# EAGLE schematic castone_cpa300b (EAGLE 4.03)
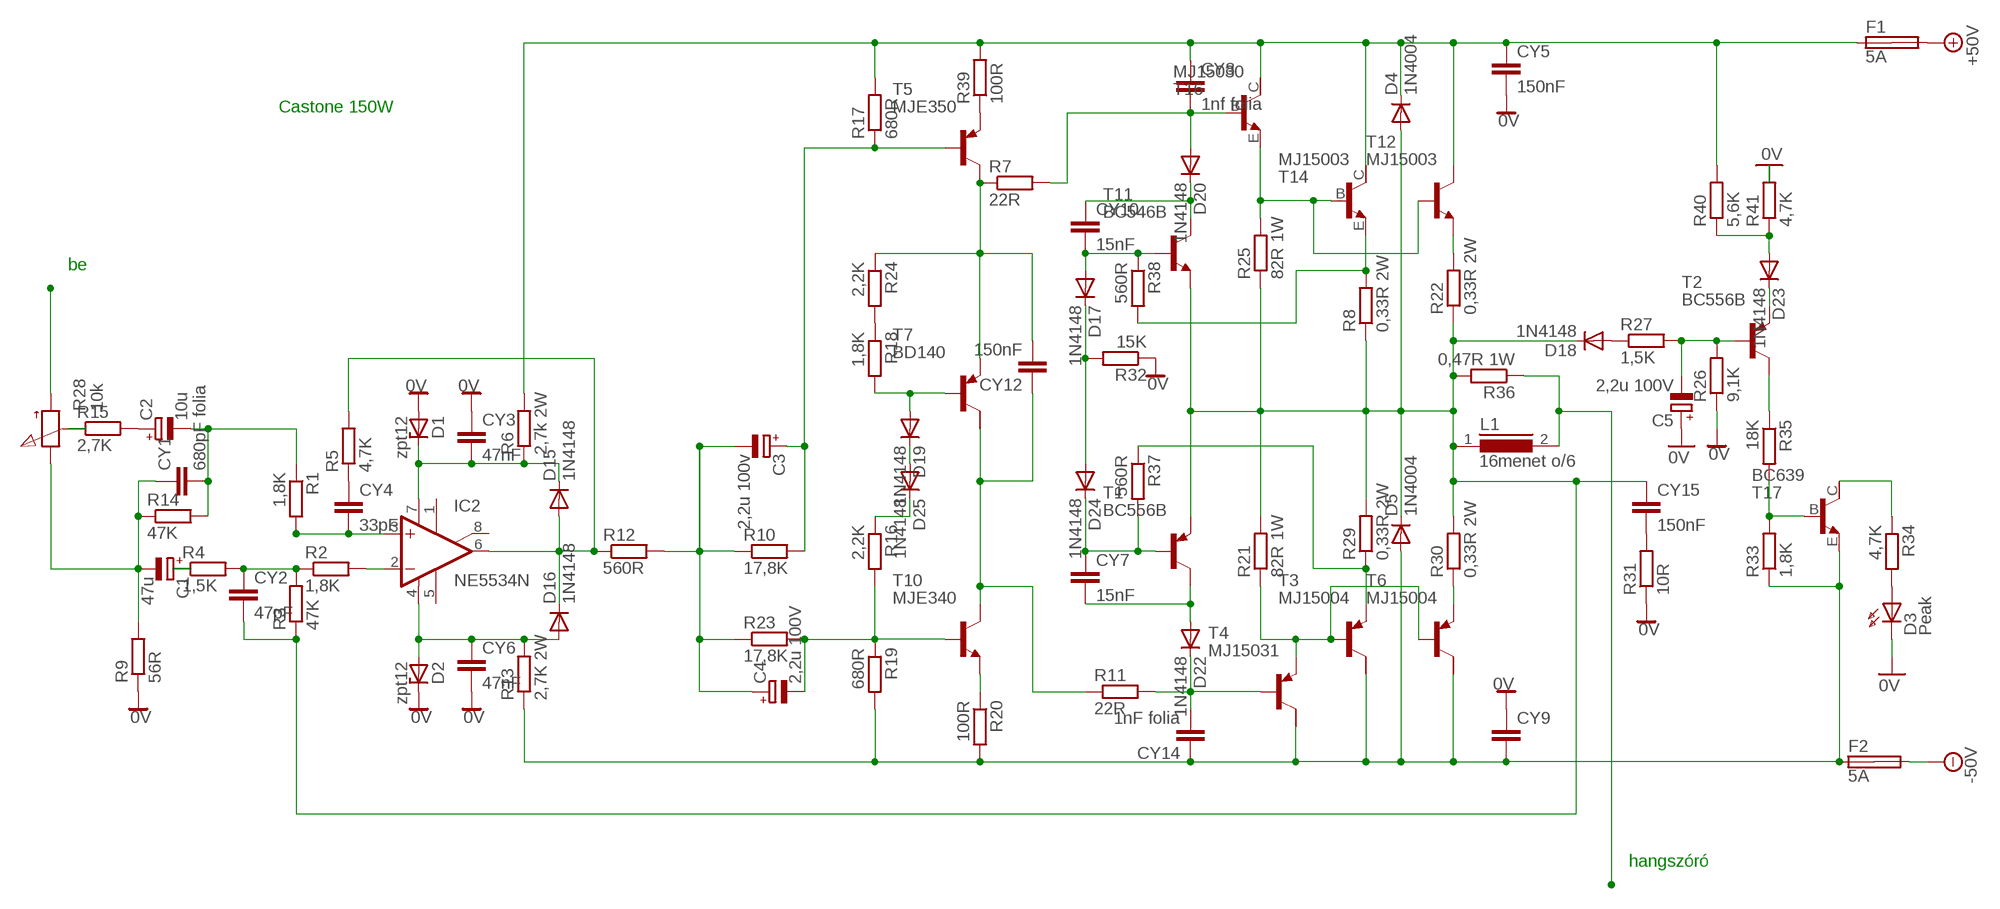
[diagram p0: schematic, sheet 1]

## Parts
C1  47u  CPOL-EUTT6D6  [TT5D6]
C2  10u  CPOL-EUTT6D6  [TT5D6]
C3  2,2u 100v  CPOL-EUTT6D6  [TT5D6]
C4  2,2u 100V  CPOL-EUTT6D6  [TT5D6]
C5  2,2u 100V  CPOL-EUTT6D6  [TT5D6]
CY1  680pF folia  CYYC15B6  [YC15B6]
CY2  47pF  CYYC10B5  [YC10B5]
CY3  47nF  CYYC10B5  [YC10B5]
CY4  33pF  CYYC10B5  [YC10B5]
CY5  150nF  CYYC10B5  [YC10B5]
CY6  47nF  CYYC10B5  [YC10B5]
CY7  15nF  CYYC10B5  [YC10B5]
CY8  1nf folia  CYYC10B5  [YC10B5]
CY9  CYYC10B5  [YC10B5]
CY10  15nF  CYYC10B5  [YC10B5]
CY12  150nF  CYYC10B5  [YC10B5]
CY14  1nF folia  CYYC10B5  [YC10B5]
CY15  150nF  CYYC10B5  [YC10B5]
D1  zpt12  ZTK  [DO35Z10]
D2  zpt12  ZTK  [DO35Z10]
D3  Peak  IRL80A  [IRL80A]
D4  1N4004  [DO41-10]
D5  1N4004  [DO41-10]
D15  1N4148  [DO35-10]
D16  1N4148  [DO35-10]
D17  1N4148  [DO35-10]
D18  1N4148  [DO35-10]
D19  1N4148  [DO35-10]
D20  1N4148  [DO35-10]
D22  1N4148  [DO35-10]
D23  1N4148  [DO35-10]
D24  1N4148  [DO35-10]
D25  1N4148  [DO35-10]
F1  5A  SHK20Q  [SHK20Q]
F2  5A  SHK20Q  [SHK20Q]
IC2  NE5534N  [DIL08]
L1  16menet o/6  SMSC20  [SMSC20]
R1  1,8K  R-EU_V526-0  [V526-0]
R2  1,8K  R-EU_V526-0  [V526-0]
R3  47K  R-EU_V526-0  [V526-0]
R4  1,5K  R-EU_V526-0  [V526-0]
R5  4,7K  R-EU_V526-0  [V526-0]
R6  2,7k 2W  R-EU_V526-0  [V526-0]
R7  22R  R-EU_V526-0  [V526-0]
R8  0,33R 2W  R-EU_0204/5  [0204/5]
R9  56R  R-EU_V526-0  [V526-0]
R10  17,8K  R-EU_V526-0  [V526-0]
R11  22R  R-EU_V526-0  [V526-0]
R12  560R  R-EU_V526-0  [V526-0]
R13  2,7K 2W  R-EU_V526-0  [V526-0]
R14  47K  R-EU_V526-0  [V526-0]
R15  2,7K  R-EU_V526-0  [V526-0]
R16  2,2K  R-EU_V526-0  [V526-0]
R17  680R  R-EU_V526-0  [V526-0]
R18  1,8K  R-EU_V526-0  [V526-0]
R19  680R  R-EU_V526-0  [V526-0]
R20  100R  R-EU_V526-0  [V526-0]
R21  82R 1W  R-EU_V526-0  [V526-0]
R22  0,33R 2W  R-EU_0204/5  [0204/5]
R23  17,8K  R-EU_V526-0  [V526-0]
R24  2,2K  R-EU_V526-0  [V526-0]
R25  82R 1W  R-EU_V526-0  [V526-0]
R26  9,1K  R-EU_V526-0  [V526-0]
R27  1,5K  R-EU_V526-0  [V526-0]
R28  10k  PC25  [PC25]
R29  0,33R 2W  R-EU_0204/5  [0204/5]
R30  0,33R 2W  R-EU_0204/5  [0204/5]
R31  10R  R-EU_0204/5  [0204/5]
R32  15K  R-EU_0204/5  [0204/5]
R33  1,8K  R-EU_0204/5  [0204/5]
R34  4,7K  R-EU_0204/5  [0204/5]
R35  18K  R-EU_0204/5  [0204/5]
R36  0,47R 1W  R-EU_0204/5  [0204/5]
R37  560R  R-EU_0204/5  [0204/5]
R38  560R  R-EU_0204/5  [0204/5]
R39  100R  R-EU_0204/7  [0204/7]
R40  5,6K  R-EU_0204/5  [0204/5]
R41  4,7K  R-EU_0204/5  [0204/5]
T1  BC556B  MJE350  [TO126]
T2  BC556B  MJE350  [TO126]
T3  MJ15004  MJ2955  [TO3]
T4  MJ15031  MJ2955  [TO3]
T5  MJE350  [TO126]
T6  MJ15004  MJ2955  [TO3]
T7  BD140  MJ2955  [TO3]
T10  MJE340  [TO126]
T11  BC546B  MJE340  [TO126]
T12  MJ15003  MJE340  [TO126]
T14  MJ15003  MJ413  [TO3]
T16  MJ15030  MJ413  [TO3]
T17  BC639  MJ413  [TO3]

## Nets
0V: C5.+ CY3.2 CY5.1 CY6.1 CY9.2 D1.A D2.C D3.K(C) R9.1 R26.1 R31.1 R32.1 R41.2
+24V: F1.2A ; supply symbol labelled +50V
-24V: F2.2A ; supply symbol labelled -50V
N$1: IC2.2(-IN) R2.2
N$2: CY4.2 R5.1
N$3: C1.+ R4.1
N$5: CY15.1 R31.2
N$6: CY10.2 D20.C T11.2(C)
N$7: CY3.1 D1.C D15.C IC2.7(V+) R6.1
N$8: CY6.2 D2.A D16.A IC2.4(V-) R13.2
N$9: R15.1 R28.S
N$10: CY4.1 IC2.3(+IN) R1.2
N$11: CY2.2 R2.1 R3.2 R4.2
N$12: D15.A D16.C IC2.6(OUT) R5.2 R12.1
N$13: C2.- CY1.1 R1.1 R14.2
N$14: C1.- CY1.2 R9.2 R14.1 R28.A
N$15: CY2.1 CY15.2 D4.A D5.C D18.C L1.1 R3.1 R8.1 R21.2 R22.1 R25.1 R29.2 R30.2 R36.2 T1.1(E) T11.1(E)
N$16: C2.+ R15.2
N$17: CY12.1 R7.1 R24.1 T5.2(C) T7.E
N$18: C3.- C4.+ R10.1 R12.2 R23.1
N$19: C3.+ R10.2 R17.1 T5.3(B)
N$20: CY14.1 D22.C R11.2 T4.B
N$21: CY5.2 CY8.2 D4.C F1.1A R6.2 R17.2 R39.2 R40.2 T12.2(C) T14.C T16.C
N$22: CY7.1 D22.A T1.2(C)
N$23: C4.- R16.2 R19.1 R23.2 T10.3(B)
N$24: R21.1 T3.B T4.E T6.B
N$25: R20.1 T10.1(E)
N$26: CY9.1 CY14.2 D5.A F2.1A R13.1 R19.2 R20.2 R33.1 T3.C T4.C T6.C T17.E
N$27: D19.C D25.A
N$28: D25.C R16.1
N$29: C5.- R26.2 R27.2 T2.3(B)
N$30: R18.2 T7.B
N$31: R18.1 R24.2
N$32: L1.2 R36.1
N$33: R35.1 T2.2(C)
N$34: R29.1 R37.1 T3.E
N$35: R30.1 T6.E
N$36: R8.2 R38.2 T14.E
N$37: R22.2 T12.1(E)
N$38: CY7.2 D24.C R37.2 T1.3(B)
N$39: R33.2 R35.2 T17.B
N$40: CY8.1 D20.A R7.2 T16.B
N$41: CY10.1 D17.A R38.1 T11.3(B)
N$42: R34.1 T17.C
N$43: D17.C D24.A R32.2
N$44: R25.2 T12.3(B) T14.B T16.E
N$45: D3.A R34.2
N$46: D23.C T2.1(E)
N$47: D23.A R40.1 R41.1
N$48: D18.A R27.1
N$49: R28.E
N$50: R39.1 T5.1(E)
N$51: CY12.2 R11.1 T7.C T10.2(C)
N$52: D19.A
Unconnected: F1.1B F1.2B F2.1B F2.2B IC2.1(ON) IC2.5(CMP) IC2.8(ON/CMP) T3.C/ T4.C/ T6.C/ T7.C/ T14.C/(C) T16.C/(C) T17.C/(C)

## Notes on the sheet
- Castone 150W
- be
- hangszóró

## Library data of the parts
C1-C5 = rcl:CPOL-EU: POLARIZED CAPACITOR, European symbol
CY1-CY10 CY12 CY14 CY15 = rcl:CY: Y CAPACITOR
D1 D2 = diode:ZTK: Z DIODE
D3 = led:IRL80A: IR LED
D4 D5 = diode:1N4004: DIODE
D15-D20 D22-D25 = diode:1N4148: DIODE
F1 F2 = fuse:SHK20Q: FUSE HOLDER 5 x 20 mm, SH contact, E1207 Buerklin
IC2 = linear:NE5534: AUDIO AMPLIFIER
L1 = inductors:SMSC20: INDUCTOR
R1-R27 R29-R41 = rcl:R-EU_: RESISTOR, European symbol
R28 = pot-vitrohm:PC25: VITROHM POTENTIOMETER
T1 T2 T5 = transistor-pnp:MJE350: PNP TRANSISTOR
T3 T4 T6 T7 = transistor-pnp:MJ2955: PNP TRANSISTOR
T10-T12 = transistor-npn:MJE340: NPN TRANSISTOR
T14 T16 T17 = transistor-npn:MJ413: NPN TRANSISTOR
